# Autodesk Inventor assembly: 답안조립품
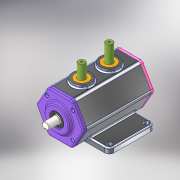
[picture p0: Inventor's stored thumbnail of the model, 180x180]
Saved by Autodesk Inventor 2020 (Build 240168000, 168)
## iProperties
Created: 2021-06
Part Number: 답안조립품
Document SubType Name: Assembly
Designer: 605-13
Author: 605-13
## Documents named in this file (11)
- C:\Users\605-13\Desktop\710606V1004\답안조립품.iam
- C:\Users\605-13\Desktop\710606V1004\본체.ipt
- C:\Users\605-13\Desktop\710606V1004\앞커버.ipt
- C:\Users\605-13\Desktop\710606V1004\뒷커버.ipt
- C:\Users\605-13\Desktop\710606V1004\부시.ipt
- C:\Users\605-13\Desktop\710606V1004\오일실.ipt
- C:\Users\605-13\Desktop\710606V1004\베어링 6203.ipt
- C:\Users\605-13\Desktop\710606V1004\편심축.ipt
- C:\Users\605-13\Desktop\710606V1004\베어링 6302.ipt
- C:\Users\605-13\Desktop\710606V1004\슬라이더.ipt
- C:\Users\605-13\Desktop\710606V1004\볼트 M4.ipt
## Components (10 placed, 3 different names)
1. 8-오일실:1
2. 7-베어링 6203:1
3. 9-M4-소켓머리:2
4. 9-M4-소켓머리:3
5. 9-M4-소켓머리:4
6. 9-M4-소켓머리:5
7. 9-M4-소켓머리:1
8. 9-M4-소켓머리:6
9. 9-M4-소켓머리:7
10. 9-M4-소켓머리:8
